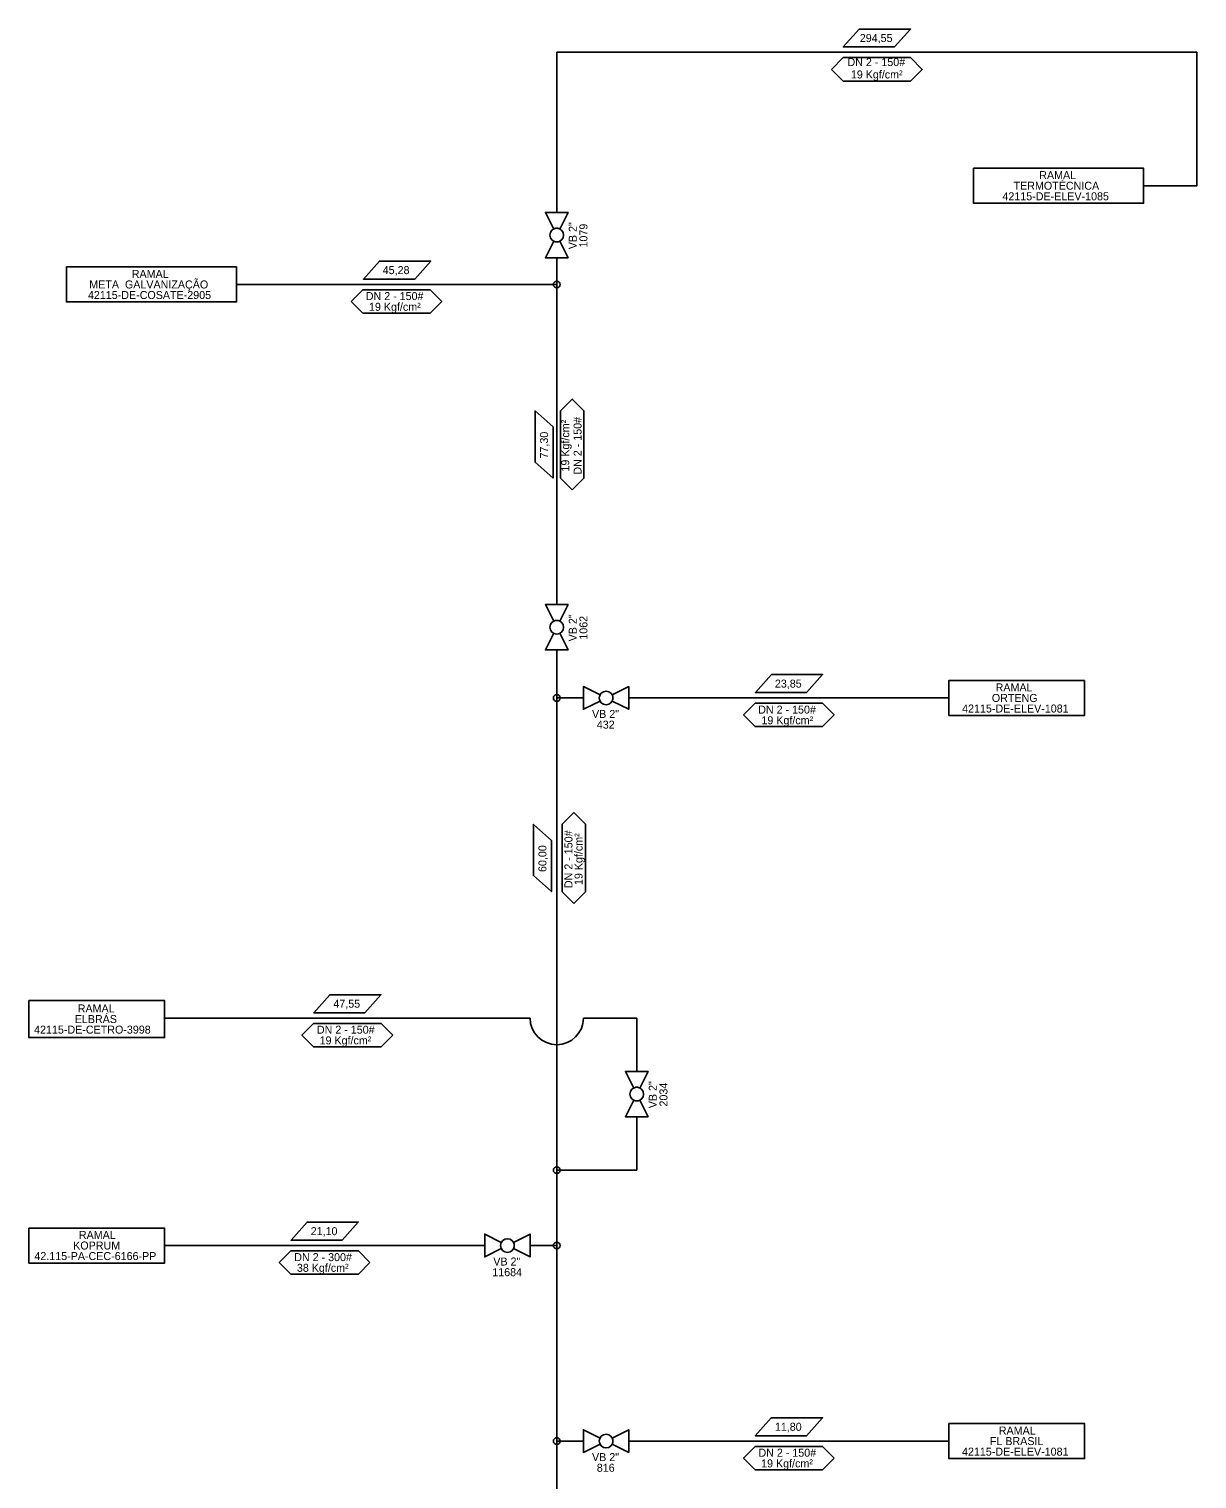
# Model space of a CAD drawing. Extents: x -39999 to 23586, y -25927 to 32541.
# Drawn here: x -37315 to -36877, y 2658 to 3201 of the extents above; entities that cross this region are included whole.
import ezdxf

# ---------------------------------------------------------------- set-up
doc = ezdxf.new("R2010")
doc.units = 0
for name, color, linetype in [('SIMBOLO', 7, 'Continuous'), ('TEXTO', 7, 'Continuous'), ('TUBO_ACO_GN_2', 7, 'Continuous'), ('VALVULA_ACO_2', 7, 'Continuous')]:
    doc.layers.add(name, color=color, linetype=linetype)

# ---------------------------------------------------------------- blocks, each defined once
blk = doc.blocks.new('VALVULA_ACO_2')
at = {"layer": 'VALVULA_ACO_2'}
for points in [[(-1.14, 0.57), (-4.25, 2.13), (-4.25, -2.13), (-1.14, -0.57)], [(-1.14, -0.57), (-4.25, -2.13), (-4.25, 2.13), (-1.14, 0.57)], [(1.14, -0.57), (4.25, -2.13), (4.25, 2.13), (1.14, 0.57)], [(1.14, -0.57), (4.25, -2.13), (4.25, 2.13), (1.14, 0.57)]]:
    blk.add_lwpolyline(points, dxfattribs=at)
blk.add_circle((0, 0), 1.28, dxfattribs=at)
for start, end in [(90, 270), (153.4349, 206.5651), (270, 90), (0, 26.5651), (333.4349, 0)]:
    blk.add_arc((0, 0), 1.28, start, end, dxfattribs=at)

msp = doc.modelspace()

# ---------------------------------------------------------------- linework, layer by layer
at = {"layer": 'SIMBOLO'}
for points in [[(-36990.62, 3194.5), (-37009.84, 3194.5), (-37003.84, 3201.24), (-36984.62, 3201.24)], [(-36961.05, 3149.06), (-36897.23, 3149.06), (-36897.23, 3135.93), (-36961.05, 3135.93)], [(-37237.23, 3112.05), (-37301.05, 3112.05), (-37301.05, 3098.92), (-37237.23, 3098.92)], [(-37170.49, 3107.48), (-37189.71, 3107.48), (-37183.71, 3114.23), (-37164.49, 3114.23)], [(-37125.37, 3038.87), (-37125.37, 3058.09), (-37118.62, 3052.09), (-37118.62, 3032.87)], [(-37023.56, 2952.47), (-37042.78, 2952.47), (-37036.78, 2959.22), (-37017.56, 2959.22)], [(-36919.39, 2957.03), (-36970.22, 2957.03), (-36970.22, 2943.91), (-36919.39, 2943.91)], [(-37119.23, 2897.08), (-37119.23, 2877.86), (-37125.98, 2883.86), (-37125.98, 2903.08)], [(-37189.12, 2832.47), (-37208.34, 2832.47), (-37202.34, 2839.22), (-37183.12, 2839.22)], [(-37315.07, 2837.03), (-37264.24, 2837.03), (-37264.24, 2823.16), (-37315.07, 2823.16)], [(-37315.07, 2751.77), (-37264.24, 2751.77), (-37264.24, 2738.65), (-37315.07, 2738.65)], [(-37197.63, 2747.21), (-37216.85, 2747.21), (-37210.85, 2753.96), (-37191.63, 2753.96)], [(-37023.61, 2673.89), (-37042.82, 2673.89), (-37036.82, 2680.64), (-37017.61, 2680.64)], [(-36970.22, 2678.45), (-36919.39, 2678.45), (-36919.39, 2665.33), (-36970.22, 2665.33)]]:
    msp.add_lwpolyline(points, close=True, dxfattribs=at)
for points in [[(-37014.23, 3186.12), (-37009.85, 3190.5), (-36984.6, 3190.5), (-36980.23, 3186.12), (-36984.6, 3181.75), (-37009.85, 3181.75), (-37014.23, 3186.12)], [(-37194.36, 3099.11), (-37189.98, 3094.73), (-37164.73, 3094.73), (-37160.36, 3099.11), (-37164.73, 3103.48), (-37189.98, 3103.48), (-37194.36, 3099.11)], [(-37111.41, 3028.48), (-37107.04, 3032.86), (-37107.04, 3058.11), (-37111.41, 3062.48), (-37115.79, 3058.11), (-37115.79, 3032.86), (-37111.41, 3028.48)], [(-37047.26, 2944.1), (-37042.89, 2939.72), (-37017.64, 2939.72), (-37013.26, 2944.1), (-37017.64, 2948.47), (-37042.89, 2948.47), (-37047.26, 2944.1)], [(-37110.85, 2873.47), (-37115.23, 2877.85), (-37115.23, 2903.1), (-37110.85, 2907.47), (-37106.48, 2903.1), (-37106.48, 2877.85), (-37110.85, 2873.47)], [(-37178.73, 2824.1), (-37183.11, 2819.72), (-37208.36, 2819.72), (-37212.73, 2824.1), (-37208.36, 2828.47), (-37183.11, 2828.47), (-37178.73, 2824.1)], [(-37187.24, 2738.84), (-37191.61, 2734.46), (-37216.86, 2734.46), (-37221.24, 2738.84), (-37216.86, 2743.21), (-37191.61, 2743.21), (-37187.24, 2738.84)], [(-37013.22, 2665.51), (-37017.59, 2661.14), (-37042.84, 2661.14), (-37047.22, 2665.51), (-37042.84, 2669.89), (-37017.59, 2669.89), (-37013.22, 2665.51)]]:
    msp.add_lwpolyline(points, dxfattribs=at)
for centre in [(-37117.23, 3105.48), (-37117.23, 2950.47), (-37117.23, 2773.46), (-37117.23, 2745.21), (-37117.23, 2671.89)]:
    msp.add_circle(centre, 1.27, dxfattribs=at)
at = {"layer": 'TUBO_ACO_GN_2'}
for p, q in [((-37117.23, 3132.5), (-37117.23, 3192.5)), ((-37117.23, 3192.5), (-36877.23, 3192.5)), ((-37117.23, 2985.48), (-37117.23, 3115.48)), ((-37117.23, 3105.48), (-37237.23, 3105.48)), ((-37117.23, 2968.47), (-37117.23, 2551.89)), ((-37107.23, 2950.47), (-37117.23, 2950.47)), ((-36970.22, 2950.47), (-37090.22, 2950.47)), ((-37127.23, 2830.47), (-37264.24, 2830.47)), ((-37264.24, 2745.21), (-37144.24, 2745.21)), ((-37117.23, 2745.21), (-37127.23, 2745.21)), ((-37107.23, 2671.89), (-37117.23, 2671.89)), ((-36970.22, 2671.89), (-37090.22, 2671.89))]:
    msp.add_line(p, q, dxfattribs=at)
for points in [[(-36877.23, 3192.5), (-36877.23, 3142.5), (-36897.23, 3142.5)], [(-37087.23, 2810.47), (-37087.23, 2830.47), (-37107.23, 2830.47)], [(-37117.23, 2773.46), (-37087.23, 2773.46), (-37087.23, 2793.46)]]:
    msp.add_lwpolyline(points, dxfattribs=at)
msp.add_arc((-37117.23, 2830.47), 10, 180, 0, dxfattribs=at)

# ---------------------------------------------------------------- block references
at = {"layer": 'VALVULA_ACO_2', "xscale": 2, "yscale": 2, "rotation": 90}
for p in [(-37117.23, 3123.99), (-37117.23, 2976.98), (-37087.23, 2801.97)]:
    msp.add_blockref('VALVULA_ACO_2', p, dxfattribs=at)
at = {"layer": 'VALVULA_ACO_2', "xscale": 2, "yscale": 2}
for p in [(-37098.72, 2950.47), (-37135.73, 2745.21), (-37098.72, 2671.89)]:
    msp.add_blockref('VALVULA_ACO_2', p, dxfattribs=at)

# ---------------------------------------------------------------- texts
for s, p in [('VB 2"', (-37109.73, 3118.7)), ('1079', (-37105.73, 3119.33)), ('VB 2"', (-37109.73, 2971.69)), ('1062', (-37105.73, 2972.32)), ('VB 2"', (-37079.73, 2796.68)), ('2034', (-37075.73, 2797.31))]:
    msp.add_text(s, height=3, rotation=90).set_placement(p)
for s, p in [('VB 2"', (-37104.01, 2942.97)), ('432', (-37102.22, 2938.97)), ('VB 2"', (-37141.02, 2737.71)), ('11684', (-37141.4, 2733.71)), ('VB 2"', (-37104.01, 2664.39)), ('816', (-37102.22, 2660.39))]:
    msp.add_text(s, height=3).set_placement(p)
at = {"layer": 'TEXTO'}
for s, p in [('294,55', (-37003.63, 3196.37)), ('DN 2 - 150#', (-37008.25, 3187.34)), ('19 Kgf/cm²', (-37006.97, 3182.71)), ('RAMAL', (-36936.36, 3144.96)), ('TERMOTÉCNICA', (-36945.99, 3141)), ('42115-DE-ELEV-1085', (-36950.16, 3137.03)), ('RAMAL', (-37276.54, 3107.94)), ('45,28', (-37182.47, 3109.36)), ('META  GALVANIZAÇÃO', (-37292.47, 3103.98)), ('42115-DE-COSATE-2905', (-37292.97, 3100.02)), ('DN 2 - 150#', (-37188.82, 3099.62)), ('19 Kgf/cm²', (-37187.61, 3095.61)), ('23,85', (-37035.46, 2954.35)), ('ORTENG', (-36954.13, 2948.97)), ('RAMAL', (-36952.71, 2952.93)), ('DN 2 - 150#', (-37041.72, 2944.61)), ('42115-DE-ELEV-1081', (-36965.27, 2945.01)), ('19 Kgf/cm²', (-37040.51, 2940.6)), ('ELBRÁS', (-37297.92, 2828.6)), ('RAMAL', (-37296.79, 2832.56)), ('47,55', (-37200.98, 2834.35)), ('42115-DE-CETRO-3998 ', (-37313.15, 2824.64)), ('DN 2 - 150#', (-37207.14, 2824.61)), ('19 Kgf/cm²', (-37206.13, 2820.6)), ('RAMAL', (-37296.37, 2747.67)), ('21,10', (-37209.48, 2749.09)), ('KOPRUM', (-37298.51, 2743.71)), ('42.115-PA-CEC-6166-PP', (-37313.04, 2739.75)), ('DN 2 - 300#', (-37215.64, 2739.35)), ('38 Kgf/cm²', (-37214.64, 2735.34)), ('11,80', (-37035.46, 2675.76)), ('RAMAL', (-36951.52, 2674.35)), ('DN 2 - 150#', (-37041.62, 2666.03)), ('42115-DE-ELEV-1081', (-36965.32, 2666.43)), ('FL BRASIL', (-36954.87, 2670.39)), ('19 Kgf/cm²', (-37040.62, 2662.02))]:
    msp.add_text(s, height=3, dxfattribs=at).set_placement(p)
for s, p in [('DN 2 - 150#', (-37107.91, 3034.19)), ('77,30', (-37120.5, 3040.24)), ('19 Kgf/cm²', (-37112.54, 3035.35)), ('DN 2 - 150#', (-37111.35, 2879.18)), ('19 Kgf/cm²', (-37107.55, 2880.34)), ('60,00', (-37121.1, 2885.23))]:
    msp.add_text(s, height=3, rotation=90, dxfattribs=at).set_placement(p)

doc.saveas('drawing.dxf')
